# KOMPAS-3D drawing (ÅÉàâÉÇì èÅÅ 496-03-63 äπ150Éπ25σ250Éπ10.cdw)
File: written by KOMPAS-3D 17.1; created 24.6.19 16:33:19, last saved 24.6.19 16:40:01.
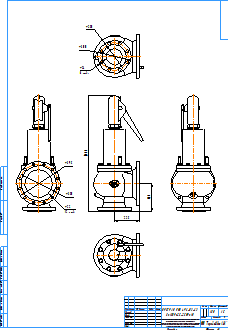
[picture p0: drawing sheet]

Sheet 1: A2, portrait

Title block, sheet 1: name: ПРЕГРАН КПП 496-03-63 / Ду150Ру25х250Ру10; material: Сталь 10  ГОСТ 1050-88; mass: 180; sheets: 1; sheet format: A2; stored path: \\adlc.lan\data\АДЛ_ПКД\3D-модели\ADL production\Предохранительные клапаны ПРЕГРАН\ПРЕГРАН 496\ПРЕГРАН КПП 496-03-63\KOMPAS 2D\ПРЕГРАН КПП 496-03-63 Ду150Ру25х250Ру10.cdw

Views: Вид 1, Проекционный вид 4, Проекционный вид 5
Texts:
  kka
  adl
  Рама для чертежей
  Лит-Масса-Масштаб
  Материал-Предприятие
  Масштаб
  Изм.
  Лист
  № докум.
  Подп.
  Дата
  Лит.
  Разраб.
  Пров.
  Т.контр.
  Листов
  Внимание! Данный продукт является объектом авторского права ООО «Торговый Дом АДЛ».
  Запрещается изменение, копирование, распространение
  (в том числе путем копирования на другие сайты и ресурсы в Интернете)
  или любое иное использование информации и объектов без предварительного
  согласия правообладателя (ООО «Торговый Дом АДЛ»).
  Н.контр.
  Утв.
  ООО "Торговый дом АДЛ"
  Изменение
  Номер документа
  Подпись
  Обозначение документа
  Наименование изделия
  Масса изделия по ГОСТ 2.109-73
  Порядковый номер листа
  Общее количество листов в документе
  Характер работы, выполненной лицом, подписавшим документ
  Наименование или индекс предприятия, выпускающего документ
  Инв. № подл.
  Подп. и дата
  Взам. инв. №
  Инв. № дубл.
  Инвентарный номер подлинника по ГОСТ 2.501-68
  Подпись принявшего подлинник в отдел технической документации
  Инвентарный номер подлинника, взамен которого выпущен данный подлинник
  Инвентарный номер дубликата по ГОСТ 2.502-68
  Подпись принявшего дубликат в отдел технической документации
  Справ. №
  Перв. примен.
  Обозначение документа, взамен или на основании которого выпущен данный документ
  Обозначение документа, в котором впервые записан данный документ
  Подпись лица, копировавшего чертеж
  Обозначение формата листа
  !Рама для чертежа
Dimensions and other numbers on the sheet: 1029; 225; 245; 250; 300; 26; 8 отв.; 1:5; 1; 180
